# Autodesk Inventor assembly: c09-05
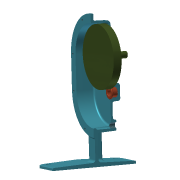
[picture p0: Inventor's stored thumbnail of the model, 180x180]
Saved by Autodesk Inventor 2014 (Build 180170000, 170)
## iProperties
Created: 2010-12
Part Number: c09-05
Document SubType Name: Assembly
Designer: Thom Tremblay
Author: Thom Tremblay
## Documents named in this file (4)
- C:\Inventor 2014 Essentials\Assemblies\Chapter 09\c09-05.iam
- C:\Inventor 2014 Essentials\Content Center Files\en-US\ISO 2795  F\ISO 2795 - 10 x 14 x 10F.ipt
- C:\Inventor 2014 Essentials\Parts\Chapter 09\c09-11.ipt
- C:\Inventor 2014 Essentials\Assemblies\Chapter 09\Design Accelerators\Blank Input Shaft 1.iam
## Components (4 placed, 3 different names)
1. c09-11:1 — Insert:27, Insert:28
2. ISO 2795 (Flanged) 10 x 14 x 10:2 — Insert:27
3. ISO 2795 (Flanged) 10 x 14 x 10:3 — Insert:28, Insert:29
4. Blank Input Shaft 1:1 [sub-assembly] — Insert:29
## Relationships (3: Insert 3)
- Insert:27: c09-11:1 ↔ ISO 2795 (Flanged) 10 x 14 x 10:2
- Insert:28: c09-11:1 ↔ ISO 2795 (Flanged) 10 x 14 x 10:3
- Insert:29: ISO 2795 (Flanged) 10 x 14 x 10:3 ↔ Blank Input Shaft 1:1
